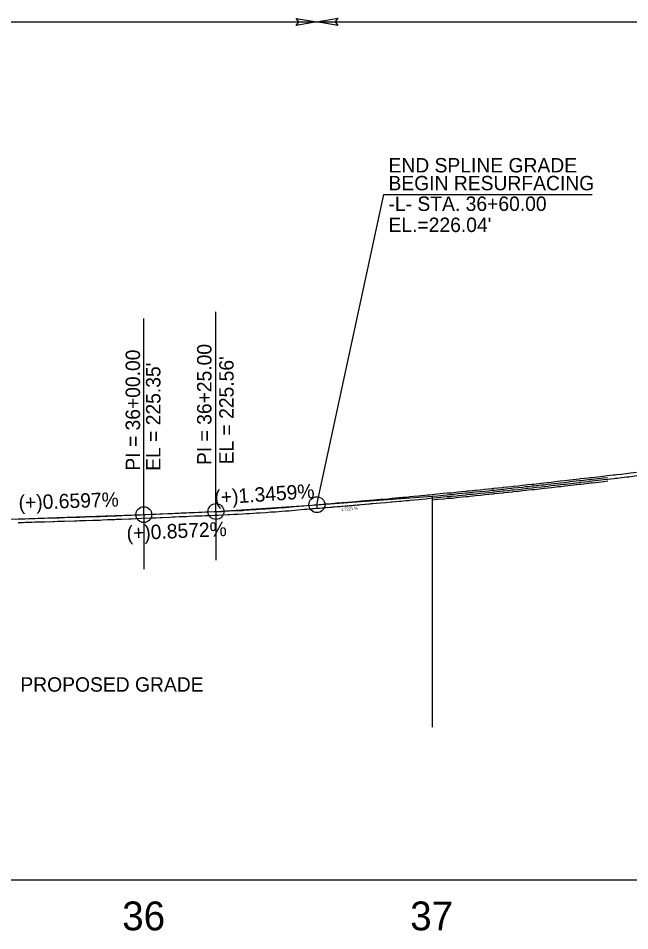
# Model space of a CAD drawing. Extents: x 2115752 to 2121174, y 562881 to 567245.
# Drawn here: x 2119252.8 to 2119464.8, y 566358.2 to 566674.8 of the extents above; entities that cross this region are included whole.
import ezdxf

# ---------------------------------------------------------------- set-up
doc = ezdxf.new("R2010")
doc.units = 0
for name, color, linetype in [('Exist Profile Cell', 7, 'Continuous'), ('Exist Vertical Profile Ground Line', 7, 'Continuous'), ('Exist Vertical Profile Horizontal Axis Label Major', 7, 'Continuous'), ('Prop Vertical Profile Grade', 7, 'Continuous'), ('Prop Vertical Profile Grade Label', 7, 'Continuous'), ('Prop VPI Label', 7, 'Continuous'), ('Scratch_Level_1', 7, 'Continuous')]:
    doc.layers.add(name, color=color, linetype=linetype)

msp = doc.modelspace()

# ---------------------------------------------------------------- linework, layer by layer
at = {"layer": 'Exist Profile Cell'}
msp.add_line((2116696.3, 566375.81), (2121174.42, 566375.81), dxfattribs=at)
at = {"layer": 'Exist Vertical Profile Ground Line'}
for points in [[(2119325.41, 566502.58), (2119326.07, 566502.61), (2119327.52, 566502.69), (2119328.9, 566502.76), (2119330.55, 566502.79), (2119331.97, 566502.93), (2119332.4, 566502.96), (2119332.86, 566502.99), (2119334.31, 566503.07), (2119335.36, 566503.12), (2119336.51, 566503.2), (2119338.6, 566503.34), (2119339.35, 566503.39), (2119340.35, 566503.47), (2119341.26, 566503.5), (2119341.93, 566503.57), (2119344.15, 566503.74), (2119345.26, 566503.83), (2119346.55, 566503.9), (2119348.62, 566504.11), (2119351.86, 566504.41), (2119352.88, 566504.49), (2119354.7, 566504.63), (2119355.42, 566504.69), (2119357.19, 566504.78), (2119358.52, 566504.95), (2119359.44, 566505.03), (2119361.5, 566505.19), (2119361.8, 566505.21), (2119362.47, 566505.26), (2119363.34, 566505.36), (2119364.34, 566505.41), (2119365.16, 566505.5), (2119367.05, 566505.66), (2119368.47, 566505.77), (2119370.92, 566505.99), (2119371.76, 566506.06), (2119374.7, 566506.34), (2119375.09, 566506.37), (2119378.37, 566506.67), (2119380.23, 566506.73), (2119381.89, 566506.94), (2119382.39, 566506.99), (2119384.9, 566507.21), (2119385.46, 566507.26), (2119386.19, 566507.34), (2119387.32, 566507.41), (2119388.17, 566507.51), (2119388.69, 566507.56), (2119390.07, 566507.69), (2119391.57, 566507.83), (2119392.65, 566507.9), (2119393.97, 566508.09), (2119394.81, 566508.16), (2119395.48, 566508.23), (2119398.12, 566508.5), (2119400.23, 566508.72), (2119401.5, 566508.83), (2119402.28, 566508.87), (2119403.24, 566508.92), (2119404.65, 566509.13), (2119405.43, 566509.22), (2119407.95, 566509.47), (2119408.52, 566509.52), (2119409.26, 566509.61), (2119410.35, 566509.69), (2119411.27, 566509.8), (2119413.01, 566509.97), (2119414.55, 566510.12), (2119415.87, 566510.22), (2119417.03, 566510.37), (2119417.49, 566510.41), (2119417.84, 566510.45), (2119420.77, 566510.77), (2119421.1, 566510.8), (2119422.67, 566510.98), (2119423.93, 566511.12), (2119424.44, 566511.18), (2119426.29, 566511.32), (2119427.63, 566511.51), (2119428.69, 566511.64), (2119429.47, 566511.72), (2119430.97, 566511.87), (2119431.63, 566511.93), (2119432.46, 566512.05), (2119434.22, 566512.23), (2119435.17, 566512.3), (2119436.3, 566512.46), (2119437.53, 566512.61), (2119440.01, 566512.9), (2119440.79, 566512.99), (2119442.32, 566513.13), (2119444.21, 566513.4), (2119447.32, 566513.74), (2119447.82, 566513.8), (2119450.56, 566514.1), (2119451.1, 566514.16), (2119451.77, 566514.24), (2119453.87, 566514.47), (2119455.61, 566514.69), (2119457.13, 566514.86)], [(2119457.13, 566514.86), (2119459.3, 566515.12), (2119459.86, 566515.16), (2119460.36, 566515.23), (2119461.91, 566515.39), (2119463.7, 566515.63), (2119464.41, 566515.72), (2119467.25, 566516.09)], [(2119252.75, 566499.83), (2119253.65, 566499.85), (2119254.42, 566499.86), (2119255.16, 566499.9), (2119257.43, 566499.97), (2119258.5, 566500), (2119259.72, 566500.03), (2119261.28, 566500.07), (2119261.89, 566500.09), (2119264.8, 566500.2), (2119265.23, 566500.21), (2119266.35, 566500.23), (2119266.86, 566500.24), (2119268.82, 566500.31), (2119272.31, 566500.42), (2119273.14, 566500.44), (2119273.97, 566500.46), (2119275.27, 566500.52), (2119276.24, 566500.55), (2119278.64, 566500.64), (2119279.18, 566500.66), (2119279.94, 566500.68), (2119281.04, 566500.69), (2119282, 566500.75), (2119283.65, 566500.81), (2119285.35, 566500.87), (2119286.28, 566500.91), (2119286.74, 566500.93), (2119287.42, 566500.95), (2119288.17, 566500.94), (2119288.72, 566500.99), (2119291.11, 566501.09), (2119292.01, 566501.13), (2119293.53, 566501.2), (2119295.42, 566501.27), (2119298.78, 566501.42), (2119300.51, 566501.46), (2119302, 566501.55), (2119302.68, 566501.58), (2119305.44, 566501.7), (2119306.23, 566501.74), (2119307.13, 566501.78), (2119308.66, 566501.85), (2119309.28, 566501.89), (2119310.03, 566501.92), (2119311.12, 566501.92), (2119312.05, 566502), (2119313.92, 566502.08), (2119315.34, 566502.13), (2119316.4, 566502.16), (2119317.73, 566502.22), (2119318.29, 566502.22), (2119318.69, 566502.25), (2119320.72, 566502.34), (2119321.33, 566502.37), (2119322.02, 566502.4), (2119323.52, 566502.44), (2119325.41, 566502.58)]]:
    msp.add_lwpolyline(points, dxfattribs=at)
at = {"layer": 'Prop Vertical Profile Grade'}
msp.add_lwpolyline([(2118985.32, 566512.53), (2119042.37, 566507.63), (2119066.3, 566505.62), (2119096.3, 566503.52), (2119121.3, 566502.32), (2119146.3, 566501.33), (2119171.3, 566500.63), (2119206.3, 566500.08), (2119246.3, 566500.91), (2119296.3, 566502.56), (2119321.3, 566503.63), (2119356.3, 566505.99)], dxfattribs=at)
at = {"layer": 'Prop VPI Label'}
for p, q in [((2119356.3, 566505.99), (2119379.56, 566613.59)), ((2119379.56, 566613.59), (2119451.72, 566613.59)), ((2119296.3, 566502.56), (2119296.3, 566570.61)), ((2119321.3, 566503.63), (2119321.3, 566572.98))]:
    msp.add_line(p, q, dxfattribs=at)
for centre in [(2119356.3, 566505.99), (2119296.3, 566502.56), (2119321.3, 566503.63)]:
    msp.add_circle(centre, 2.75, dxfattribs=at)
at = {"layer": 'Scratch_Level_1'}
for p, q in [((2118985.32, 566673.51), (2119356.3, 566673.51)), ((2119356.3, 566673.51), (2119727.28, 566673.51)), ((2119356.3, 566505.99), (2119396.3, 566508.95)), ((2119396.3, 566508.95), (2119396.3, 566428.85)), ((2119355.42, 566504.69), (2119378.37, 566506.67)), ((2119356.3, 566505.99), (2119356.3, 566504.73)), ((2119296.3, 566502.56), (2119296.3, 566483.58)), ((2119321.3, 566503.62), (2119321.3, 566486.73))]:
    msp.add_line(p, q, dxfattribs=at)
for points in [[(2119349.1, 566674.75), (2119356.3, 566673.51), (2119349.06, 566672.23), (2119349.98, 566673.51)], [(2119363.5, 566672.27), (2119356.3, 566673.51), (2119363.54, 566674.79), (2119362.62, 566673.51)]]:
    msp.add_lwpolyline(points, close=True, dxfattribs=at)
for points in [[(2119456.98, 566516.1), (2119459.17, 566516.36), (2119459.72, 566516.41), (2119460.21, 566516.48), (2119461.76, 566516.63), (2119463.53, 566516.87), (2119464.25, 566516.96), (2119467.11, 566517.33)], [(2119325.35, 566503.83), (2119326, 566503.86), (2119327.45, 566503.94), (2119328.86, 566504.01), (2119330.48, 566504.04), (2119331.87, 566504.18), (2119332.32, 566504.21), (2119332.79, 566504.23), (2119334.24, 566504.31), (2119335.29, 566504.37), (2119336.42, 566504.45), (2119338.52, 566504.59), (2119339.27, 566504.64), (2119340.28, 566504.72), (2119341.18, 566504.75), (2119341.82, 566504.81), (2119344.05, 566504.99), (2119345.18, 566505.08), (2119346.46, 566505.15), (2119348.5, 566505.35), (2119351.76, 566505.65), (2119352.78, 566505.74), (2119354.6, 566505.88), (2119355.34, 566505.94), (2119357.07, 566506.02), (2119358.39, 566506.19), (2119359.34, 566506.27), (2119361.4, 566506.44), (2119361.7, 566506.46), (2119362.35, 566506.51), (2119363.24, 566506.61), (2119364.25, 566506.66), (2119365.04, 566506.74), (2119366.95, 566506.9), (2119368.36, 566507.01), (2119370.82, 566507.24), (2119371.65, 566507.3), (2119374.59, 566507.58), (2119374.98, 566507.62), (2119378.3, 566507.92), (2119380.13, 566507.97), (2119381.75, 566508.19), (2119382.27, 566508.23), (2119384.8, 566508.46), (2119385.34, 566508.5), (2119386.08, 566508.59), (2119387.2, 566508.66), (2119388.04, 566508.76), (2119388.57, 566508.81), (2119389.95, 566508.93), (2119391.48, 566509.08), (2119392.52, 566509.14), (2119393.83, 566509.33), (2119394.69, 566509.41), (2119395.35, 566509.48), (2119398, 566509.75), (2119400.11, 566509.96), (2119401.42, 566510.08), (2119402.22, 566510.12), (2119403.12, 566510.16), (2119404.49, 566510.37), (2119405.3, 566510.46), (2119407.83, 566510.72), (2119408.4, 566510.76), (2119409.14, 566510.85), (2119410.23, 566510.94), (2119411.13, 566511.04), (2119412.89, 566511.21), (2119414.44, 566511.37), (2119415.74, 566511.47), (2119416.9, 566511.61), (2119417.37, 566511.65), (2119417.69, 566511.69), (2119420.64, 566512.01), (2119420.97, 566512.04), (2119422.53, 566512.22), (2119423.79, 566512.36), (2119424.32, 566512.42), (2119426.16, 566512.56), (2119427.47, 566512.75), (2119428.56, 566512.88), (2119429.34, 566512.96), (2119430.85, 566513.12), (2119431.49, 566513.17), (2119432.31, 566513.29), (2119434.11, 566513.47), (2119435.03, 566513.54), (2119436.14, 566513.7), (2119437.39, 566513.85), (2119439.86, 566514.14), (2119440.65, 566514.23), (2119442.18, 566514.37), (2119444.06, 566514.64), (2119447.18, 566514.98), (2119447.69, 566515.04), (2119450.42, 566515.34), (2119450.95, 566515.4), (2119451.63, 566515.48), (2119453.72, 566515.71), (2119455.46, 566515.93), (2119456.99, 566516.1)], [(2119396.3, 566508.95), (2119398.06, 566509.13), (2119400.17, 566509.34), (2119401.46, 566509.46), (2119402.25, 566509.5), (2119403.18, 566509.54), (2119404.57, 566509.75), (2119405.37, 566509.84), (2119407.89, 566510.1), (2119408.46, 566510.14), (2119409.2, 566510.23), (2119410.29, 566510.32), (2119411.2, 566510.42), (2119412.95, 566510.59), (2119414.49, 566510.74), (2119415.81, 566510.85), (2119416.97, 566510.99), (2119417.43, 566511.03), (2119417.76, 566511.07), (2119420.71, 566511.39), (2119421.04, 566511.42), (2119422.6, 566511.6), (2119423.86, 566511.74), (2119424.38, 566511.8), (2119426.22, 566511.94), (2119427.55, 566512.13), (2119428.62, 566512.26), (2119429.4, 566512.34), (2119430.91, 566512.5), (2119431.56, 566512.55), (2119432.38, 566512.67), (2119434.16, 566512.85), (2119435.1, 566512.92), (2119436.22, 566513.08), (2119437.46, 566513.23), (2119439.94, 566513.52), (2119440.72, 566513.61), (2119442.25, 566513.75), (2119444.14, 566514.02), (2119447.25, 566514.36), (2119447.75, 566514.42), (2119450.49, 566514.72), (2119451.02, 566514.78), (2119451.7, 566514.86), (2119453.8, 566515.09), (2119455.53, 566515.31), (2119457.06, 566515.48)], [(2119396.3, 566507.69), (2119398.19, 566507.88), (2119400.29, 566508.09), (2119401.55, 566508.21), (2119402.31, 566508.25), (2119403.3, 566508.3), (2119404.73, 566508.51), (2119405.5, 566508.59), (2119408, 566508.85), (2119408.58, 566508.9), (2119409.32, 566508.99), (2119410.41, 566509.07), (2119411.33, 566509.18), (2119413.07, 566509.35), (2119414.6, 566509.5), (2119415.94, 566509.6), (2119417.1, 566509.75), (2119417.55, 566509.79), (2119417.91, 566509.83), (2119420.84, 566510.14), (2119421.17, 566510.18), (2119422.74, 566510.36), (2119424, 566510.5), (2119424.5, 566510.56), (2119426.36, 566510.7), (2119427.71, 566510.9), (2119428.76, 566511.02), (2119429.53, 566511.1), (2119431.03, 566511.25), (2119431.7, 566511.31), (2119432.53, 566511.43), (2119434.27, 566511.61), (2119435.24, 566511.68), (2119436.38, 566511.84), (2119437.61, 566511.99), (2119440.08, 566512.28), (2119440.85, 566512.37), (2119442.39, 566512.51), (2119444.29, 566512.78), (2119447.39, 566513.12), (2119447.89, 566513.17), (2119450.63, 566513.48), (2119451.17, 566513.54), (2119451.84, 566513.62), (2119453.94, 566513.84), (2119455.68, 566514.06), (2119457.2, 566514.24)], [(2119252.73, 566501.08), (2119253.62, 566501.1), (2119254.38, 566501.11), (2119255.12, 566501.14), (2119257.39, 566501.22), (2119258.46, 566501.25), (2119259.68, 566501.28), (2119261.25, 566501.32), (2119261.84, 566501.34), (2119264.77, 566501.45), (2119265.21, 566501.46), (2119266.32, 566501.48), (2119266.83, 566501.49), (2119268.77, 566501.56), (2119272.28, 566501.67), (2119273.12, 566501.69), (2119273.93, 566501.71), (2119275.22, 566501.77), (2119276.19, 566501.8), (2119278.6, 566501.89), (2119279.14, 566501.9), (2119279.92, 566501.93), (2119281, 566501.94), (2119281.94, 566502), (2119283.6, 566502.06), (2119285.3, 566502.12), (2119286.24, 566502.16), (2119286.7, 566502.18), (2119287.4, 566502.2), (2119288.11, 566502.19), (2119288.64, 566502.24), (2119291.06, 566502.34), (2119291.96, 566502.38), (2119293.48, 566502.44), (2119295.37, 566502.52), (2119298.74, 566502.67), (2119300.46, 566502.71), (2119301.94, 566502.8), (2119302.63, 566502.83), (2119305.39, 566502.95), (2119306.18, 566502.99), (2119307.07, 566503.03), (2119308.59, 566503.1), (2119309.22, 566503.14), (2119310, 566503.17), (2119311.07, 566503.17), (2119311.97, 566503.24), (2119313.87, 566503.32), (2119315.3, 566503.38), (2119316.35, 566503.41), (2119317.7, 566503.47), (2119318.24, 566503.47), (2119318.61, 566503.5), (2119320.66, 566503.59), (2119321.27, 566503.62), (2119321.98, 566503.65), (2119323.45, 566503.69), (2119325.32, 566503.83)]]:
    msp.add_lwpolyline(points, dxfattribs=at)

# ---------------------------------------------------------------- texts
at = {"layer": 'Exist Vertical Profile Horizontal Axis Label Major'}
for s, p in [('36', (2119288.79, 566358.31)), ('37', (2119388.65, 566358.31))]:
    msp.add_text(s, height=10, dxfattribs=at).set_placement(p)
at = {"layer": 'Prop Vertical Profile Grade Label'}
for s, rotation, p in [('(+)0.6597%', 1.8892, (2119252.94, 566504.23)), ('(+)1.3459%', 3.85, (2119320.92, 566506)), ('(+)0.8572%', 2.4542, (2119290.42, 566493.64))]:
    msp.add_text(s, height=5, rotation=rotation, dxfattribs=at).set_placement(p)
at = {"layer": 'Prop VPI Label'}
for s, p in [('END SPLINE GRADE', (2119381.12, 566621.29)), ('BEGIN RESURFACING', (2119381.12, 566615.09)), ('-L- STA. 36+60.00', (2119381.12, 566607.94)), ("EL.=226.04'", (2119381.12, 566600.61)), ('PROPOSED GRADE', (2119253.48, 566441.12))]:
    msp.add_text(s, height=5, dxfattribs=at).set_placement(p)
for s, p in [('PI = 36+25.00', (2119319.74, 566519.77)), ('PI = 36+00.00', (2119294.98, 566517.81)), ("EL = 225.35'", (2119302.05, 566517.76)), ("EL = 225.56'", (2119327.43, 566519.98))]:
    msp.add_text(s, height=5, rotation=90, dxfattribs=at).set_placement(p)
at = {"layer": 'Scratch_Level_1'}
msp.add_text('1.7221 %', height=1, rotation=4.9213, dxfattribs=at).set_placement((2119364.69, 566503.8))

doc.saveas('drawing.dxf')
